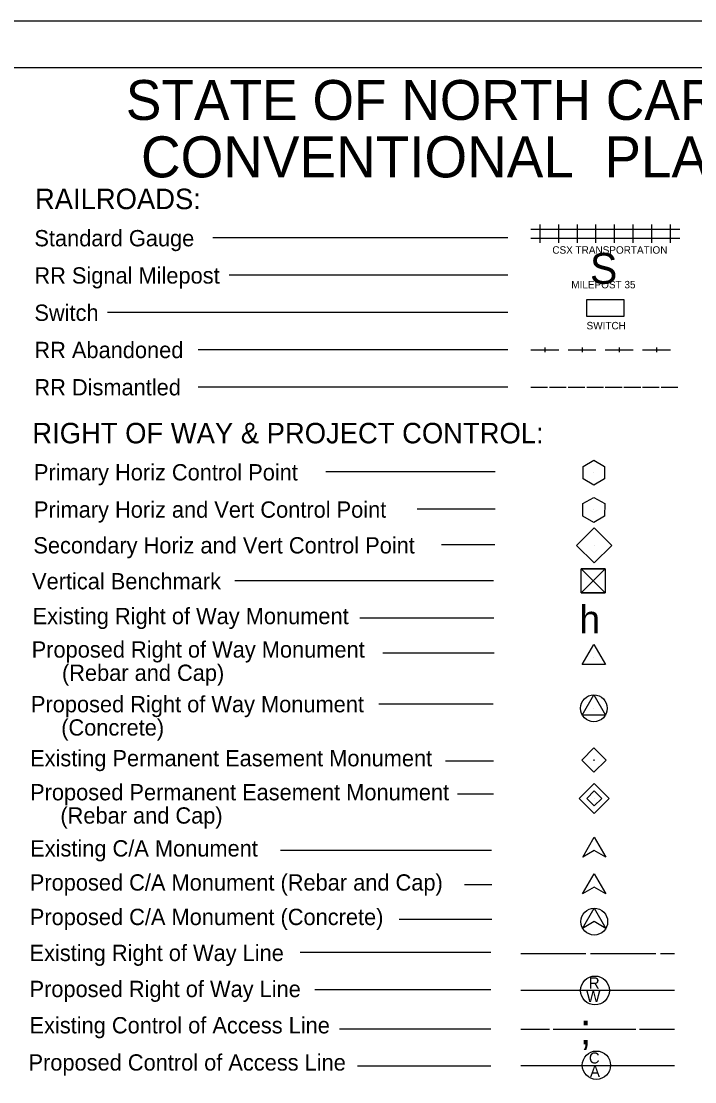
# Model space of a CAD drawing. Extents: x 573077.9 to 573111.9, y -55204.3 to -55182.3.
# Drawn here: x 573089.24 to 573096.48, y -55193.68 to -55182.3 of the extents above; entities that cross this region are included whole.
import ezdxf

# ---------------------------------------------------------------- set-up
doc = ezdxf.new("R2010")
doc.units = 0
for name, color, linetype in [('Default', 7, 'Continuous'), ('Prop ROW Permanent Easement CELL', 7, 'Continuous'), ('Sheet Plot Border Inside CELL', 7, 'Continuous'), ('Sheet Symbology CELL', 7, 'Continuous')]:
    doc.layers.add(name, color=color, linetype=linetype)

msp = doc.modelspace()

# ---------------------------------------------------------------- linework, layer by layer
at = {"layer": 'Default'}
for p, q in [((573095.392, -55187.144), (573095.392, -55187.144)), ((573095.391, -55187.544), (573095.391, -55187.544)), ((573095.394, -55187.925), (573095.394, -55187.925)), ((573095.384, -55188.305), (573095.384, -55188.305)), ((573095.393, -55190.23), (573095.393, -55190.23))]:
    msp.add_line(p, q, dxfattribs=at)
for points in [[(573095.392, -55187.278), (573095.276, -55187.212), (573095.276, -55187.079), (573095.392, -55187.011), (573095.507, -55187.077), (573095.507, -55187.212), (573095.392, -55187.278)], [(573095.514, -55188.176), (573095.254, -55188.435), (573095.384, -55188.306), (573095.514, -55188.435), (573095.254, -55188.176)], [(573095.384, -55188.306), (573095.514, -55188.176), (573095.254, -55188.176), (573095.384, -55188.306)], [(573095.384, -55188.306), (573095.254, -55188.435), (573095.514, -55188.435), (573095.384, -55188.306)]]:
    msp.add_lwpolyline(points, dxfattribs=at)
for points in [[(573095.275, -55187.476), (573095.392, -55187.411), (573095.509, -55187.475), (573095.507, -55187.61), (573095.39, -55187.678), (573095.275, -55187.613)], [(573095.206, -55187.925), (573095.395, -55187.736), (573095.584, -55187.925), (573095.395, -55188.114)], [(573095.254, -55188.176), (573095.514, -55188.176), (573095.514, -55188.435), (573095.254, -55188.435)], [(573095.263, -55190.23), (573095.393, -55190.1), (573095.523, -55190.23), (573095.393, -55190.36)]]:
    msp.add_lwpolyline(points, close=True, dxfattribs=at)
msp.add_circle((573095.393, -55190.23), 0.00253, dxfattribs=at)
at = {"layer": 'Prop ROW Permanent Easement CELL'}
msp.add_line((573095.397, -55190.642), (573095.397, -55190.642), dxfattribs=at)
for points in [[(573095.397, -55190.481), (573095.558, -55190.642), (573095.397, -55190.803), (573095.236, -55190.642)], [(573095.397, -55190.561), (573095.477, -55190.642), (573095.397, -55190.722), (573095.316, -55190.642)]]:
    msp.add_lwpolyline(points, close=True, dxfattribs=at)
at = {"layer": 'Sheet Plot Border Inside CELL'}
msp.add_lwpolyline([(573077.854, -55204.298), (573111.854, -55204.298), (573111.854, -55182.298), (573077.854, -55182.298)], close=True, dxfattribs=at)
at = {"layer": 'Sheet Symbology CELL'}
for p, q in [((573094.815, -55184.679), (573094.815, -55184.479)), ((573095.015, -55184.679), (573095.015, -55184.479)), ((573095.215, -55184.679), (573095.215, -55184.479)), ((573095.415, -55184.679), (573095.415, -55184.479)), ((573095.615, -55184.679), (573095.615, -55184.479)), ((573095.815, -55184.679), (573095.815, -55184.479)), ((573096.015, -55184.679), (573096.015, -55184.479)), ((573096.215, -55184.679), (573096.215, -55184.479)), ((573094.715, -55184.529), (573094.915, -55184.529)), ((573094.915, -55184.529), (573095.115, -55184.529)), ((573095.115, -55184.529), (573095.315, -55184.529)), ((573095.315, -55184.529), (573095.515, -55184.529)), ((573095.515, -55184.529), (573095.715, -55184.529)), ((573095.715, -55184.529), (573095.915, -55184.529)), ((573095.915, -55184.529), (573096.115, -55184.529)), ((573096.115, -55184.529), (573096.315, -55184.529)), ((573094.467, -55184.625), (573091.298, -55184.625)), ((573094.715, -55184.629), (573094.915, -55184.629)), ((573094.915, -55184.629), (573095.115, -55184.629)), ((573095.115, -55184.629), (573095.315, -55184.629)), ((573095.315, -55184.629), (573095.515, -55184.629)), ((573095.515, -55184.629), (573095.715, -55184.629)), ((573095.715, -55184.629), (573095.915, -55184.629)), ((573095.915, -55184.629), (573096.115, -55184.629)), ((573096.115, -55184.629), (573096.315, -55184.629)), ((573094.467, -55185.025), (573091.476, -55185.025)), ((573094.467, -55185.425), (573090.168, -55185.425)), ((573094.467, -55185.825), (573091.143, -55185.825)), ((573094.715, -55185.825), (573095.015, -55185.825)), ((573094.865, -55185.8), (573094.865, -55185.85)), ((573095.115, -55185.825), (573095.415, -55185.825)), ((573095.265, -55185.8), (573095.265, -55185.85)), ((573095.515, -55185.825), (573095.815, -55185.825)), ((573095.665, -55185.8), (573095.665, -55185.85)), ((573095.915, -55185.825), (573096.215, -55185.825)), ((573096.065, -55185.8), (573096.065, -55185.85)), ((573094.467, -55186.225), (573091.143, -55186.225)), ((573094.467, -55186.225), (573091.143, -55186.225)), ((573094.715, -55186.225), (573094.895, -55186.225)), ((573094.915, -55186.225), (573095.095, -55186.225)), ((573095.115, -55186.225), (573095.295, -55186.225)), ((573095.315, -55186.225), (573095.495, -55186.225)), ((573095.515, -55186.225), (573095.695, -55186.225)), ((573095.715, -55186.225), (573095.895, -55186.225)), ((573095.915, -55186.225), (573096.095, -55186.225)), ((573096.115, -55186.225), (573096.295, -55186.225)), ((573094.333, -55187.137), (573092.512, -55187.137)), ((573094.333, -55187.537), (573093.495, -55187.537)), ((573094.327, -55187.921), (573093.756, -55187.921)), ((573094.313, -55188.306), (573091.536, -55188.306)), ((573094.319, -55188.705), (573092.878, -55188.705)), ((573094.321, -55189.081), (573093.126, -55189.081)), ((573095.391, -55189.133), (573095.391, -55189.133)), ((573094.311, -55189.629), (573093.081, -55189.629)), ((573095.392, -55189.674), (573095.392, -55189.674)), ((573094.313, -55190.243), (573093.797, -55190.243)), ((573094.313, -55190.595), (573093.927, -55190.595)), ((573095.272, -55191.273), (573095.397, -55191.057)), ((573095.397, -55191.057), (573095.522, -55191.273)), ((573094.293, -55191.2), (573092.028, -55191.2)), ((573095.397, -55191.201), (573095.272, -55191.273)), ((573095.522, -55191.273), (573095.397, -55191.201)), ((573095.271, -55191.666), (573095.396, -55191.45)), ((573095.396, -55191.45), (573095.521, -55191.666)), ((573094.295, -55191.57), (573094.003, -55191.57)), ((573095.396, -55191.594), (573095.271, -55191.666)), ((573095.521, -55191.666), (573095.396, -55191.594)), ((573095.271, -55192.036), (573095.396, -55191.82)), ((573095.396, -55191.82), (573095.521, -55192.036)), ((573094.295, -55191.94), (573093.301, -55191.94)), ((573095.396, -55191.964), (573095.271, -55192.036)), ((573095.521, -55192.036), (573095.396, -55191.964)), ((573094.286, -55192.296), (573092.236, -55192.296)), ((573094.607, -55192.307), (573095.307, -55192.307)), ((573095.357, -55192.307), (573096.057, -55192.307)), ((573096.107, -55192.307), (573096.257, -55192.307)), ((573094.286, -55192.696), (573092.395, -55192.696)), ((573094.607, -55192.698), (573096.257, -55192.698)), ((573094.286, -55193.118), (573092.66, -55193.118)), ((573094.607, -55193.118), (573094.916, -55193.118)), ((573094.956, -55193.118), (573095.844, -55193.118)), ((573095.884, -55193.118), (573096.257, -55193.118)), ((573094.286, -55193.515), (573092.853, -55193.515)), ((573094.607, -55193.507), (573096.257, -55193.507))]:
    msp.add_line(p, q, dxfattribs=at)
for points in [[(573111.354, -55182.798), (573081.354, -55182.798), (573081.354, -55203.778), (573111.354, -55203.778)], [(573095.315, -55185.285), (573095.715, -55185.285), (573095.715, -55185.467), (573095.315, -55185.467)], [(573095.266, -55189.205), (573095.391, -55188.989), (573095.516, -55189.205)], [(573095.267, -55189.746), (573095.392, -55189.53), (573095.517, -55189.746)]]:
    msp.add_lwpolyline(points, close=True, dxfattribs=at)
for centre, radius in [((573095.392, -55189.674), 0.144), ((573095.396, -55191.964), 0.144), ((573095.404, -55192.703), 0.155), ((573095.42, -55193.505), 0.152)]:
    msp.add_circle(centre, radius, dxfattribs=at)

# ---------------------------------------------------------------- texts
for s, height, p in [('STATE OF NORTH CAROLINA, DIVISION OF HIGHWAYS', 0.42838, (573090.365, -55183.358)), ('CONVENTIONAL  PLAN SHEET SYMBOLS', 0.44065, (573090.528, -55183.975)), ('RAILROADS:', 0.22, (573089.389, -55184.316)), ('Standard Gauge', 0.175, (573089.383, -55184.715)), ('S', 0.33, (573095.35, -55185.117)), ('RR Signal Milepost', 0.175, (573089.383, -55185.115)), ('Switch', 0.175, (573089.383, -55185.515)), ('RR Abandoned', 0.175, (573089.383, -55185.915)), ('RR Dismantled', 0.175, (573089.383, -55186.315)), ('RIGHT OF WAY & PROJECT CONTROL:', 0.22, (573089.361, -55186.83)), ('Primary Horiz Control Point', 0.175, (573089.378, -55187.228)), ('Primary Horiz and Vert Control Point', 0.175, (573089.378, -55187.628)), ('Secondary Horiz and Vert Control Point', 0.175, (573089.372, -55188.012)), ('Vertical Benchmark', 0.175, (573089.358, -55188.397)), ('Existing Right of Way Monument', 0.175, (573089.364, -55188.771)), ('h', 0.3, (573095.236, -55188.869)), ('Proposed Right of Way Monument', 0.175, (573089.354, -55189.13)), ('     (Rebar and Cap)', 0.175, (573089.354, -55189.38)), ('Proposed Right of Way Monument', 0.175, (573089.346, -55189.717)), ('     (Concrete)', 0.175, (573089.346, -55189.967)), ('Existing Permanent Easement Monument', 0.175, (573089.337, -55190.297)), ('Proposed Permanent Easement Monument', 0.175, (573089.337, -55190.662)), ('     (Rebar and Cap)', 0.175, (573089.337, -55190.912)), ('Existing C/A Monument', 0.175, (573089.338, -55191.265)), ('Proposed C/A Monument (Rebar and Cap)', 0.175, (573089.334, -55191.631)), ('Proposed C/A Monument (Concrete)', 0.175, (573089.334, -55192.001)), ('Existing Right of Way Line', 0.175, (573089.331, -55192.387)), ('R', 0.122, (573095.337, -55192.684)), ('Proposed Right of Way Line', 0.175, (573089.331, -55192.774)), ('W', 0.122, (573095.309, -55192.827)), ('Existing Control of Access Line', 0.175, (573089.331, -55193.164)), (';', 0.33, (573095.242, -55193.282)), ('Proposed Control of Access Line', 0.175, (573089.32, -55193.563)), ('C', 0.119, (573095.339, -55193.487)), ('A', 0.119, (573095.351, -55193.63))]:
    msp.add_text(s, height=height, dxfattribs=at).set_placement(p)
for s, p in [('CSX TRANSPORTATION', (573094.946, -55184.794)), ('MILEPOST 35', (573095.15, -55185.166)), ('SWITCH', (573095.314, -55185.606))]:
    msp.add_text(s, height=0.08, rotation=360, dxfattribs=at).set_placement(p)

doc.saveas('drawing.dxf')
